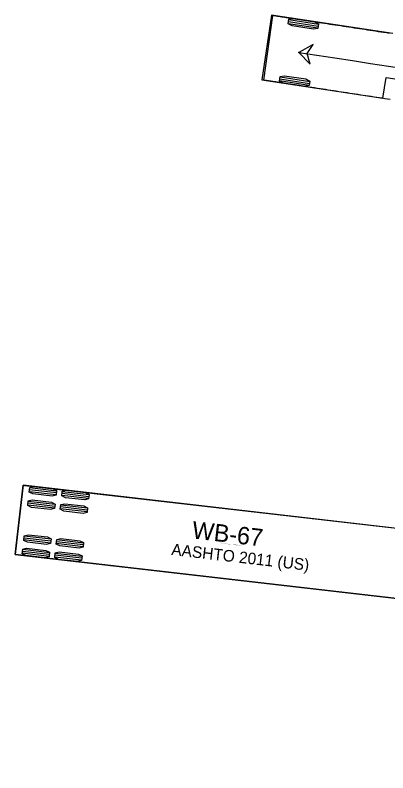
# Model space of a CAD drawing. Extents: x 2175591 to 2194071, y 76570 to 86955.
# Drawn here: x 2192642 to 2192687.6, y 86702.6 to 86795.2 of the extents above; entities that cross this region are included whole.
import ezdxf

# ---------------------------------------------------------------- set-up
doc = ezdxf.new("R2010")
doc.units = 0
doc.layers.add('-NOPLT', color=7, linetype='Continuous')
doc.layers.add('C-UTIL-STRM-TEXT', color=7, linetype='Continuous')

msp = doc.modelspace()

# ---------------------------------------------------------------- linework, layer by layer
at = {"layer": '-NOPLT'}
for p, q in [((2192673.37, 86795.207), (2192672.17, 86787.297)), ((2192688.2, 86792.956), (2192673.37, 86795.207)), ((2192675.41, 86794.204), (2192679.034, 86793.649)), ((2192675.445, 86794.431), (2192679.069, 86793.875)), ((2192675.479, 86794.657), (2192679.104, 86794.102)), ((2192674.38, 86787.428), (2192678.005, 86786.872)), ((2192674.415, 86787.655), (2192678.039, 86787.099)), ((2192687, 86785.046), (2192687.385, 86787.584)), ((2192687.385, 86787.584), (2192697.865, 86785.993)), ((2192672.17, 86787.297), (2192687, 86785.046)), ((2192672.17, 86787.297), (2192672.17, 86787.297)), ((2192674.346, 86787.202), (2192677.97, 86786.646))]:
    msp.add_line(p, q, dxfattribs=at)
for points in [[(2192687.889, 86784.892), (2192687.558, 86784.943), (2192687.228, 86784.993), (2192686.898, 86785.043), (2192686.568, 86785.094), (2192686.237, 86785.144), (2192685.907, 86785.194), (2192685.576, 86785.245), (2192685.246, 86785.295), (2192684.916, 86785.346), (2192684.585, 86785.396), (2192684.255, 86785.446), (2192683.924, 86785.497), (2192683.594, 86785.547), (2192683.264, 86785.598), (2192682.933, 86785.648), (2192682.603, 86785.699), (2192682.272, 86785.749), (2192681.942, 86785.8), (2192681.612, 86785.85), (2192681.281, 86785.901), (2192680.952, 86785.951), (2192680.622, 86786.002), (2192680.293, 86786.052), (2192679.963, 86786.102), (2192679.634, 86786.153), (2192679.304, 86786.203), (2192678.976, 86786.254), (2192678.647, 86786.304), (2192678.319, 86786.354), (2192677.992, 86786.404), (2192677.67, 86786.453), (2192677.56, 86786.47), (2192677.451, 86786.487), (2192677.341, 86786.504), (2192677.232, 86786.521), (2192677.122, 86786.537), (2192677.012, 86786.554), (2192676.902, 86786.571), (2192676.792, 86786.588), (2192676.683, 86786.605), (2192676.573, 86786.622), (2192676.463, 86786.638), (2192676.353, 86786.655), (2192676.244, 86786.672), (2192676.134, 86786.689), (2192676.024, 86786.706), (2192675.915, 86786.722), (2192675.805, 86786.739), (2192675.695, 86786.756), (2192675.586, 86786.773), (2192675.476, 86786.79), (2192675.367, 86786.806), (2192675.258, 86786.823), (2192675.148, 86786.84), (2192675.039, 86786.857), (2192674.93, 86786.873), (2192674.821, 86786.89), (2192674.712, 86786.907), (2192674.603, 86786.924), (2192674.494, 86786.94), (2192674.385, 86786.957), (2192674.276, 86786.974), (2192674.168, 86786.99), (2192674.059, 86787.007), (2192673.951, 86787.024), (2192673.842, 86787.04), (2192673.734, 86787.057), (2192673.626, 86787.074), (2192673.518, 86787.09), (2192673.41, 86787.107), (2192673.303, 86787.123), (2192673.195, 86787.14), (2192673.088, 86787.156), (2192672.981, 86787.173), (2192672.875, 86787.189), (2192672.768, 86787.205), (2192672.662, 86787.222), (2192672.555, 86787.238), (2192672.449, 86787.254), (2192673.526, 86795.18), (2192673.552, 86795.178), (2192673.578, 86795.175), (2192673.603, 86795.171), (2192673.628, 86795.167), (2192673.652, 86795.164), (2192673.676, 86795.16), (2192673.783, 86795.144), (2192673.89, 86795.128), (2192673.997, 86795.111), (2192674.104, 86795.095), (2192674.211, 86795.079), (2192674.317, 86795.063), (2192674.425, 86795.047), (2192674.532, 86795.03), (2192674.64, 86795.014), (2192674.748, 86794.997), (2192674.856, 86794.981), (2192674.964, 86794.965), (2192675.072, 86794.948), (2192675.181, 86794.932), (2192675.289, 86794.915), (2192675.398, 86794.899), (2192675.506, 86794.882), (2192675.615, 86794.866), (2192675.724, 86794.849), (2192675.832, 86794.833), (2192675.941, 86794.816), (2192676.05, 86794.8), (2192676.159, 86794.783), (2192676.268, 86794.767), (2192676.377, 86794.75), (2192676.486, 86794.734), (2192676.594, 86794.717), (2192676.703, 86794.701), (2192676.812, 86794.684), (2192676.921, 86794.668), (2192677.03, 86794.651), (2192677.139, 86794.635), (2192677.248, 86794.618), (2192677.357, 86794.601), (2192677.466, 86794.585), (2192677.575, 86794.568), (2192677.684, 86794.552), (2192677.793, 86794.535), (2192677.902, 86794.519), (2192678.011, 86794.502), (2192678.12, 86794.486), (2192678.229, 86794.469), (2192678.338, 86794.453), (2192678.448, 86794.436), (2192678.557, 86794.419), (2192678.667, 86794.403), (2192678.776, 86794.386), (2192678.886, 86794.369), (2192679.207, 86794.321), (2192679.534, 86794.271), (2192679.861, 86794.221), (2192680.189, 86794.172), (2192680.517, 86794.122), (2192680.845, 86794.072), (2192681.173, 86794.022), (2192681.501, 86793.973), (2192681.829, 86793.923), (2192682.157, 86793.873), (2192682.485, 86793.823), (2192682.814, 86793.773), (2192683.143, 86793.723), (2192683.471, 86793.673), (2192683.8, 86793.624), (2192684.128, 86793.574), (2192684.457, 86793.524), (2192684.786, 86793.474), (2192685.114, 86793.424), (2192685.443, 86793.374), (2192685.771, 86793.324), (2192686.1, 86793.274), (2192686.429, 86793.225), (2192686.757, 86793.175), (2192687.086, 86793.125), (2192687.415, 86793.075), (2192687.743, 86793.025)], [(2192676.725, 86790.652), (2192678.109, 86789.208), (2192677.713, 86790.5), (2192678.478, 86791.615), (2192676.725, 86790.652)]]:
    msp.add_lwpolyline(points, dxfattribs=at)
for points in [[(2192675.401, 86794.148), (2192675.488, 86794.714), (2192676.021, 86794.806), (2192678.631, 86794.406), (2192679.112, 86794.158), (2192679.026, 86793.593), (2192678.492, 86793.5), (2192675.883, 86793.9)], [(2192676.725, 86790.652), (2192678.109, 86789.208), (2192677.713, 86790.5), (2192678.478, 86791.615)], [(2192674.337, 86787.145), (2192674.424, 86787.711), (2192674.957, 86787.803), (2192677.567, 86787.403), (2192678.048, 86787.155), (2192677.961, 86786.59), (2192677.428, 86786.497), (2192674.818, 86786.897)]]:
    msp.add_lwpolyline(points, close=True, dxfattribs=at)
msp.add_circle((2192676.725, 86790.652), 0.0417, dxfattribs=at)
msp.add_arc((2194674.65, 99822.88), 13184.487, 261.2840472, 261.8994114, dxfattribs=at)
at = {"layer": 'C-UTIL-STRM-TEXT'}
for p, q in [((2192642.984, 86737.74), (2192642.01, 86729.296)), ((2192695.635, 86731.665), (2192642.984, 86737.74)), ((2192647.08, 86737.036), (2192643.802, 86737.414)), ((2192647.028, 86736.581), (2192643.75, 86736.959)), ((2192647.054, 86736.809), (2192643.776, 86737.187)), ((2192651.001, 86736.122), (2192647.723, 86736.501)), ((2192651.028, 86736.35), (2192647.749, 86736.728)), ((2192651.054, 86736.578), (2192647.776, 86736.956)), ((2192646.865, 86735.169), (2192643.587, 86735.548)), ((2192646.891, 86735.397), (2192643.613, 86735.775)), ((2192646.839, 86734.942), (2192643.56, 86735.32)), ((2192650.812, 86734.483), (2192647.534, 86734.862)), ((2192650.839, 86734.711), (2192647.56, 86735.089)), ((2192650.865, 86734.939), (2192647.587, 86735.317)), ((2192646.348, 86730.687), (2192643.07, 86731.065)), ((2192646.374, 86730.914), (2192643.096, 86731.293)), ((2192646.4, 86731.142), (2192643.122, 86731.52)), ((2192650.348, 86730.456), (2192647.069, 86730.834)), ((2192650.374, 86730.684), (2192647.096, 86731.062)), ((2192650.321, 86730.228), (2192647.043, 86730.606)), ((2192642.01, 86729.296), (2192694.661, 86723.221)), ((2192646.159, 86729.048), (2192642.88, 86729.426)), ((2192646.185, 86729.275), (2192642.907, 86729.653)), ((2192646.211, 86729.503), (2192642.933, 86729.881)), ((2192650.159, 86728.817), (2192646.88, 86729.195)), ((2192650.185, 86729.044), (2192646.907, 86729.423)), ((2192650.132, 86728.589), (2192646.854, 86728.967))]:
    msp.add_line(p, q, dxfattribs=at)
for points in [[(2192881.867, 86702.593), (2192736.29, 86718.562), (2192712.089, 86721.246), (2192699.991, 86722.61), (2192642.01, 86729.296), (2192642.984, 86737.74), (2192643.16, 86737.719), (2192643.16, 86737.719)], [(2192643.16, 86737.719), (2192667.317, 86734.938), (2192691.501, 86732.186), (2192715.689, 86729.468), (2192764.077, 86724.094)]]:
    msp.add_lwpolyline(points, dxfattribs=at)
for points in [[(2192647.087, 86737.093), (2192647.021, 86736.524), (2192646.543, 86736.406), (2192644.182, 86736.679), (2192643.743, 86736.903), (2192643.809, 86737.471), (2192644.287, 86737.589), (2192646.648, 86737.317)], [(2192651.061, 86736.634), (2192650.995, 86736.066), (2192650.516, 86735.948), (2192648.156, 86736.22), (2192647.717, 86736.444), (2192647.782, 86737.012), (2192648.261, 86737.131), (2192650.621, 86736.858)], [(2192646.898, 86735.454), (2192646.832, 86734.885), (2192646.353, 86734.767), (2192643.993, 86735.039), (2192643.554, 86735.264), (2192643.619, 86735.832), (2192644.098, 86735.95), (2192646.459, 86735.678)], [(2192650.871, 86734.995), (2192650.806, 86734.427), (2192650.327, 86734.309), (2192647.967, 86734.581), (2192647.528, 86734.805), (2192647.593, 86735.373), (2192648.072, 86735.492), (2192650.432, 86735.219)], [(2192646.407, 86731.198), (2192646.341, 86730.63), (2192645.863, 86730.512), (2192643.502, 86730.784), (2192643.063, 86731.008), (2192643.129, 86731.577), (2192643.607, 86731.695), (2192645.968, 86731.423)], [(2192650.38, 86730.74), (2192650.315, 86730.172), (2192649.836, 86730.054), (2192647.476, 86730.326), (2192647.037, 86730.55), (2192647.102, 86731.118), (2192647.581, 86731.236), (2192649.941, 86730.964)], [(2192646.218, 86729.559), (2192646.152, 86728.991), (2192645.673, 86728.873), (2192643.313, 86729.145), (2192642.874, 86729.369), (2192642.939, 86729.938), (2192643.418, 86730.056), (2192645.779, 86729.783)], [(2192650.191, 86729.101), (2192650.126, 86728.533), (2192649.647, 86728.414), (2192647.287, 86728.687), (2192646.848, 86728.911), (2192646.913, 86729.479), (2192647.392, 86729.597), (2192649.752, 86729.325)]]:
    msp.add_lwpolyline(points, close=True, dxfattribs=at)

# ---------------------------------------------------------------- texts
for s, height, p in [('WB-67', 2.125, (2192663.564, 86731.258)), ('AASHTO 2011 (US)', 1.41667, (2192661.064, 86729.229)), ('(c) 2019 Transoft Solutions, Inc. All rights reserved.', 0.085, (2192667.096, 86730.637))]:
    msp.add_text(s, height=height, rotation=353.41874, dxfattribs=at).set_placement(p)

doc.saveas('drawing.dxf')
